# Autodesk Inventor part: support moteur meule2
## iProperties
Shininess: 64.0
Length Units: 11269
Angle Units: 11279
Time Units: 11290
Mass Units: 11283
Length Display Precision: 3
Angle Display Precision: 2
Compacted: True
Part Number: support moteur meule2
Document SubType Name: Modeling
Created: 2005-01
Material: Par défaut
Designer: LEGERET Philippe
Density: 0.0
Volumn: 0.0
Area: 0.0
PropertySet Name: Model Information
Control State: 0
Master: False
Checked Out: False
Author: LEGERET Philippe
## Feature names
1. Extrusion1
2. Perçage1 [Hole]
